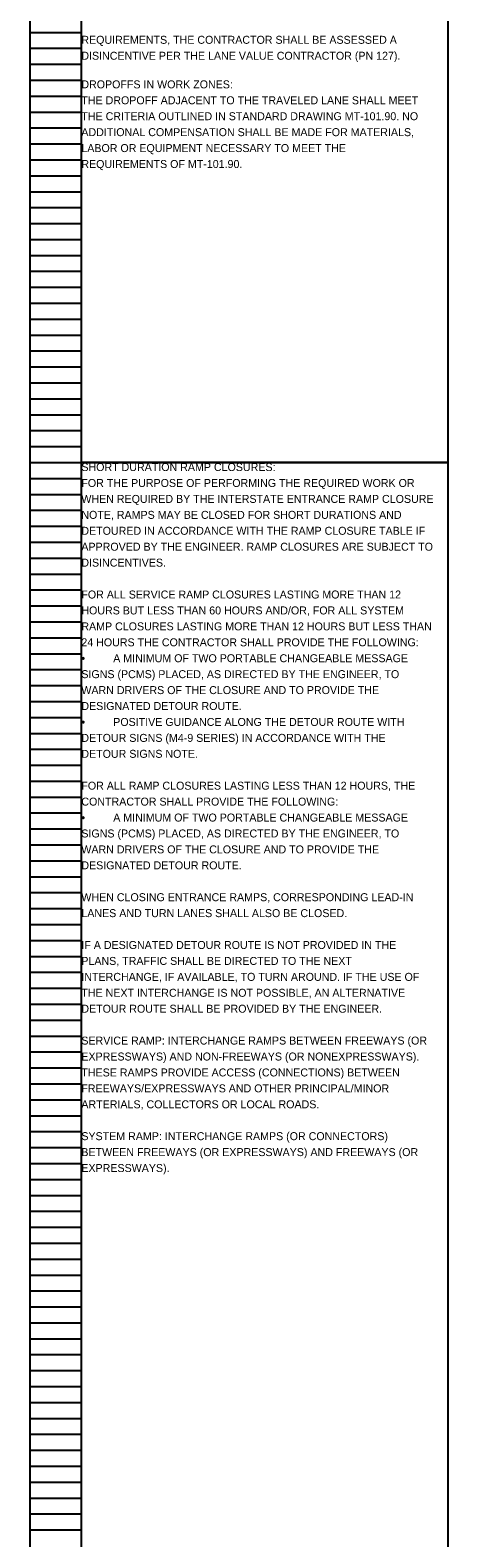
# Model space of a CAD drawing. Extents: x 16463 to 16500, y 5400 to 5823.
# Drawn here: x 16463.05 to 16470.39, y 5744.09 to 5770.59 of the extents above; entities that cross this region are included whole.
import ezdxf

# ---------------------------------------------------------------- set-up
doc = ezdxf.new("R2010")
doc.units = 0
for name, color, linetype in [('Default', 7, 'Continuous'), ('SC_Scratch1', 7, 'Continuous'), ('SH_Data', 7, 'Continuous'), ('SH_Text', 7, 'Continuous')]:
    doc.layers.add(name, color=color, linetype=linetype)

msp = doc.modelspace()

# ---------------------------------------------------------------- linework, layer by layer
at = {"layer": 'SC_Scratch1'}
for points in [[(16463.949, 5783.152), (16470.389, 5783.152), (16470.389, 5762.992), (16463.949, 5762.992)], [(16463.949, 5762.992), (16470.389, 5762.992), (16470.389, 5742.832), (16463.949, 5742.832)]]:
    msp.add_lwpolyline(points, close=True, dxfattribs=at)
at = {"layer": 'SH_Data'}
for p, q in [((16463.049, 5762.992), (16463.049, 5783.152)), ((16463.949, 5762.992), (16463.949, 5783.152)), ((16463.049, 5770.552), (16463.949, 5770.552)), ((16463.049, 5770.272), (16463.949, 5770.272)), ((16463.049, 5769.992), (16463.949, 5769.992)), ((16463.049, 5769.712), (16463.949, 5769.712)), ((16463.049, 5769.432), (16463.949, 5769.432)), ((16463.049, 5769.152), (16463.949, 5769.152)), ((16463.049, 5768.872), (16463.949, 5768.872)), ((16463.049, 5768.592), (16463.949, 5768.592)), ((16463.049, 5768.312), (16463.949, 5768.312)), ((16463.049, 5768.032), (16463.949, 5768.032)), ((16463.049, 5767.752), (16463.949, 5767.752)), ((16463.049, 5767.472), (16463.949, 5767.472)), ((16463.049, 5767.192), (16463.949, 5767.192)), ((16463.049, 5766.912), (16463.949, 5766.912)), ((16463.049, 5766.632), (16463.949, 5766.632)), ((16463.049, 5766.352), (16463.949, 5766.352)), ((16463.049, 5766.072), (16463.949, 5766.072)), ((16463.049, 5765.792), (16463.949, 5765.792)), ((16463.049, 5765.512), (16463.949, 5765.512)), ((16463.049, 5765.232), (16463.949, 5765.232)), ((16463.049, 5764.952), (16463.949, 5764.952)), ((16463.049, 5764.672), (16463.949, 5764.672)), ((16463.049, 5764.392), (16463.949, 5764.392)), ((16463.049, 5764.112), (16463.949, 5764.112)), ((16463.049, 5763.832), (16463.949, 5763.832)), ((16463.049, 5763.552), (16463.949, 5763.552)), ((16463.049, 5763.272), (16463.949, 5763.272)), ((16463.049, 5742.832), (16463.049, 5762.992)), ((16463.049, 5762.992), (16463.949, 5762.992)), ((16463.049, 5762.992), (16463.949, 5762.992)), ((16463.949, 5742.832), (16463.949, 5762.992)), ((16463.049, 5762.712), (16463.949, 5762.712)), ((16463.049, 5762.432), (16463.949, 5762.432)), ((16463.049, 5762.152), (16463.949, 5762.152)), ((16463.049, 5761.872), (16463.949, 5761.872)), ((16463.049, 5761.592), (16463.949, 5761.592)), ((16463.049, 5761.312), (16463.949, 5761.312)), ((16463.049, 5761.032), (16463.949, 5761.032)), ((16463.049, 5760.752), (16463.949, 5760.752)), ((16463.049, 5760.472), (16463.949, 5760.472)), ((16463.049, 5760.192), (16463.949, 5760.192)), ((16463.049, 5759.912), (16463.949, 5759.912)), ((16463.049, 5759.632), (16463.949, 5759.632)), ((16463.049, 5759.352), (16463.949, 5759.352)), ((16463.049, 5759.072), (16463.949, 5759.072)), ((16463.049, 5758.792), (16463.949, 5758.792)), ((16463.049, 5758.512), (16463.949, 5758.512)), ((16463.049, 5758.232), (16463.949, 5758.232)), ((16463.049, 5757.952), (16463.949, 5757.952)), ((16463.049, 5757.672), (16463.949, 5757.672)), ((16463.049, 5757.392), (16463.949, 5757.392)), ((16463.049, 5757.112), (16463.949, 5757.112)), ((16463.049, 5756.832), (16463.949, 5756.832)), ((16463.049, 5756.552), (16463.949, 5756.552)), ((16463.049, 5756.272), (16463.949, 5756.272)), ((16463.049, 5755.992), (16463.949, 5755.992)), ((16463.049, 5755.712), (16463.949, 5755.712)), ((16463.049, 5755.432), (16463.949, 5755.432)), ((16463.049, 5755.152), (16463.949, 5755.152)), ((16463.049, 5754.872), (16463.949, 5754.872)), ((16463.049, 5754.592), (16463.949, 5754.592)), ((16463.049, 5754.312), (16463.949, 5754.312)), ((16463.049, 5754.032), (16463.949, 5754.032)), ((16463.049, 5753.752), (16463.949, 5753.752)), ((16463.049, 5753.472), (16463.949, 5753.472)), ((16463.049, 5753.192), (16463.949, 5753.192)), ((16463.049, 5752.912), (16463.949, 5752.912)), ((16463.049, 5752.632), (16463.949, 5752.632)), ((16463.049, 5752.352), (16463.949, 5752.352)), ((16463.049, 5752.072), (16463.949, 5752.072)), ((16463.049, 5751.792), (16463.949, 5751.792)), ((16463.049, 5751.512), (16463.949, 5751.512)), ((16463.049, 5751.232), (16463.949, 5751.232)), ((16463.049, 5750.952), (16463.949, 5750.952)), ((16463.049, 5750.672), (16463.949, 5750.672)), ((16463.049, 5750.392), (16463.949, 5750.392)), ((16463.049, 5750.112), (16463.949, 5750.112)), ((16463.049, 5749.832), (16463.949, 5749.832)), ((16463.049, 5749.552), (16463.949, 5749.552)), ((16463.049, 5749.272), (16463.949, 5749.272)), ((16463.049, 5748.992), (16463.949, 5748.992)), ((16463.049, 5748.712), (16463.949, 5748.712)), ((16463.049, 5748.432), (16463.949, 5748.432)), ((16463.049, 5748.152), (16463.949, 5748.152)), ((16463.049, 5747.872), (16463.949, 5747.872)), ((16463.049, 5747.592), (16463.949, 5747.592)), ((16463.049, 5747.312), (16463.949, 5747.312)), ((16463.049, 5747.032), (16463.949, 5747.032)), ((16463.049, 5746.752), (16463.949, 5746.752)), ((16463.049, 5746.472), (16463.949, 5746.472)), ((16463.049, 5746.192), (16463.949, 5746.192)), ((16463.049, 5745.912), (16463.949, 5745.912)), ((16463.049, 5745.632), (16463.949, 5745.632)), ((16463.049, 5745.352), (16463.949, 5745.352)), ((16463.049, 5745.072), (16463.949, 5745.072)), ((16463.049, 5744.792), (16463.949, 5744.792)), ((16463.049, 5744.512), (16463.949, 5744.512)), ((16463.049, 5744.232), (16463.949, 5744.232))]:
    msp.add_line(p, q, dxfattribs=at)

# ---------------------------------------------------------------- texts
at = {"layer": 'Default'}
for s, p in [('REQUIREMENTS, THE CONTRACTOR SHALL BE ASSESSED A ', (16463.949, 5770.351)), ('DISINCENTIVE PER THE LANE VALUE CONTRACTOR (PN 127).', (16463.949, 5770.071))]:
    msp.add_text(s, height=0.14, dxfattribs=at).set_placement(p)
at = {"layer": 'SH_Text'}
for s, p in [('DROPOFFS IN WORK ZONES:', (16463.949, 5769.568)), ('THE DROPOFF ADJACENT TO THE TRAVELED LANE SHALL MEET ', (16463.949, 5769.288)), ('THE CRITERIA OUTLINED IN STANDARD DRAWING MT-101.90. NO ', (16463.949, 5769.008)), ('ADDITIONAL COMPENSATION SHALL BE MADE FOR MATERIALS, ', (16463.949, 5768.728)), ('LABOR OR EQUIPMENT NECESSARY TO MEET THE ', (16463.949, 5768.448)), ('REQUIREMENTS OF MT-101.90.', (16463.949, 5768.168)), ('SHORT DURATION RAMP CLOSURES:', (16463.949, 5762.842)), ('FOR THE PURPOSE OF PERFORMING THE REQUIRED WORK OR ', (16463.949, 5762.562)), ('WHEN REQUIRED BY THE INTERSTATE ENTRANCE RAMP CLOSURE ', (16463.949, 5762.282)), ('NOTE, RAMPS MAY BE CLOSED FOR SHORT DURATIONS AND ', (16463.949, 5762.002)), ('DETOURED IN ACCORDANCE WITH THE RAMP CLOSURE TABLE IF ', (16463.949, 5761.722)), ('APPROVED BY THE ENGINEER. RAMP CLOSURES ARE SUBJECT TO ', (16463.949, 5761.442)), ('DISINCENTIVES.', (16463.949, 5761.162)), ('FOR ALL SERVICE RAMP CLOSURES LASTING MORE THAN 12 ', (16463.949, 5760.602)), ('HOURS BUT LESS THAN 60 HOURS AND/OR, FOR ALL SYSTEM ', (16463.949, 5760.322)), ('RAMP CLOSURES LASTING MORE THAN 12 HOURS BUT LESS THAN ', (16463.949, 5760.042)), ('24 HOURS THE CONTRACTOR SHALL PROVIDE THE FOLLOWING:', (16463.949, 5759.762)), ('•', (16463.949, 5759.482)), ('A MINIMUM OF TWO PORTABLE CHANGEABLE MESSAGE ', (16464.509, 5759.482)), ('SIGNS (PCMS) PLACED, AS DIRECTED BY THE ENGINEER, TO ', (16463.949, 5759.202)), ('WARN DRIVERS OF THE CLOSURE AND TO PROVIDE THE ', (16463.949, 5758.922)), ('DESIGNATED DETOUR ROUTE. ', (16463.949, 5758.642)), ('•', (16463.949, 5758.362)), ('POSITIVE GUIDANCE ALONG THE DETOUR ROUTE WITH ', (16464.509, 5758.362)), ('DETOUR SIGNS (M4-9 SERIES) IN ACCORDANCE WITH THE ', (16463.949, 5758.082)), ('DETOUR SIGNS NOTE.  ', (16463.949, 5757.802)), ('FOR ALL RAMP CLOSURES LASTING LESS THAN 12 HOURS, THE ', (16463.949, 5757.242)), ('CONTRACTOR SHALL PROVIDE THE FOLLOWING:', (16463.949, 5756.962)), ('•', (16463.949, 5756.682)), ('A MINIMUM OF TWO PORTABLE CHANGEABLE MESSAGE ', (16464.509, 5756.682)), ('SIGNS (PCMS) PLACED, AS DIRECTED BY THE ENGINEER, TO ', (16463.949, 5756.402)), ('WARN DRIVERS OF THE CLOSURE AND TO PROVIDE THE ', (16463.949, 5756.122)), ('DESIGNATED DETOUR ROUTE.  ', (16463.949, 5755.842)), ('WHEN CLOSING ENTRANCE RAMPS, CORRESPONDING LEAD-IN ', (16463.949, 5755.282)), ('LANES AND TURN LANES SHALL ALSO BE CLOSED.', (16463.949, 5755.002)), ('IF A DESIGNATED DETOUR ROUTE IS NOT PROVIDED IN THE ', (16463.949, 5754.442)), ('PLANS, TRAFFIC SHALL BE DIRECTED TO THE NEXT ', (16463.949, 5754.162)), ('INTERCHANGE, IF AVAILABLE, TO TURN AROUND. IF THE USE OF ', (16463.949, 5753.882)), ('THE NEXT INTERCHANGE IS NOT POSSIBLE, AN ALTERNATIVE ', (16463.949, 5753.602)), ('DETOUR ROUTE SHALL BE PROVIDED BY THE ENGINEER. ', (16463.949, 5753.322)), ('SERVICE RAMP: INTERCHANGE RAMPS BETWEEN FREEWAYS (OR ', (16463.949, 5752.762)), ('EXPRESSWAYS) AND NON-FREEWAYS (OR NONEXPRESSWAYS). ', (16463.949, 5752.482)), ('THESE RAMPS PROVIDE ACCESS (CONNECTIONS) BETWEEN ', (16463.949, 5752.202)), ('FREEWAYS/EXPRESSWAYS AND OTHER PRINCIPAL/MINOR ', (16463.949, 5751.922)), ('ARTERIALS, COLLECTORS OR LOCAL ROADS.', (16463.949, 5751.642)), ('SYSTEM RAMP: INTERCHANGE RAMPS (OR CONNECTORS) ', (16463.949, 5751.082)), ('BETWEEN FREEWAYS (OR EXPRESSWAYS) AND FREEWAYS (OR ', (16463.949, 5750.802)), ('EXPRESSWAYS).', (16463.949, 5750.522))]:
    msp.add_text(s, height=0.14, dxfattribs=at).set_placement(p)

doc.saveas('drawing.dxf')
